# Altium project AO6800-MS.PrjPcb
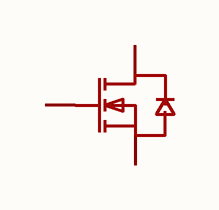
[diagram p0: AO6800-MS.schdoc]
1 sheet, 1 parts. Net scope: global (net labels, ports and power ports of the same name join across sheets).

## Sheet AO6800-MS.schdoc
size 127 x 101 mm

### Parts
Q?  ao6800-ms  [SOT-23-6_L2.9-W1.6-P0.95-LS2.7-BL]  (value not drawn)  (part A of 2)

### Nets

Not connected (* = marked no-connect by the designer): Q? 1(G) 5(S) 6(D)

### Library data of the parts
Q? = ao6800-ms: 数量:2个N沟道;漏源电压(Vdss):30V;连续漏极电流(Id):4A;导通电阻(RDS(on)):30mΩ@10V；40mΩ@4.5V;耗散功率(Pd):1.25W;阈值电压(Vgs(th)):1V@250uA;; Manufacturer: MSKSEMI(美森科); AddInBom: yes; ModelId: 396be7ac4a944b019708673e9658f3cc; ModelTransform: 108.2675,102.362,0,0,0,0,0,0,0; Number: 2个N沟道; Drain to Source Voltage: 30V; Current - Continuous Drain(Id): 4A; Pd - Power Dissipation: 1.25W; Gate Charge(Qg): 5.1nC@10V; Input Capacitance(Ciss): 333pF; Reverse Transfer Capacitance (Crss@Vds): 43pF; Type: N沟道; Output Capacitance(Coss): 52pF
